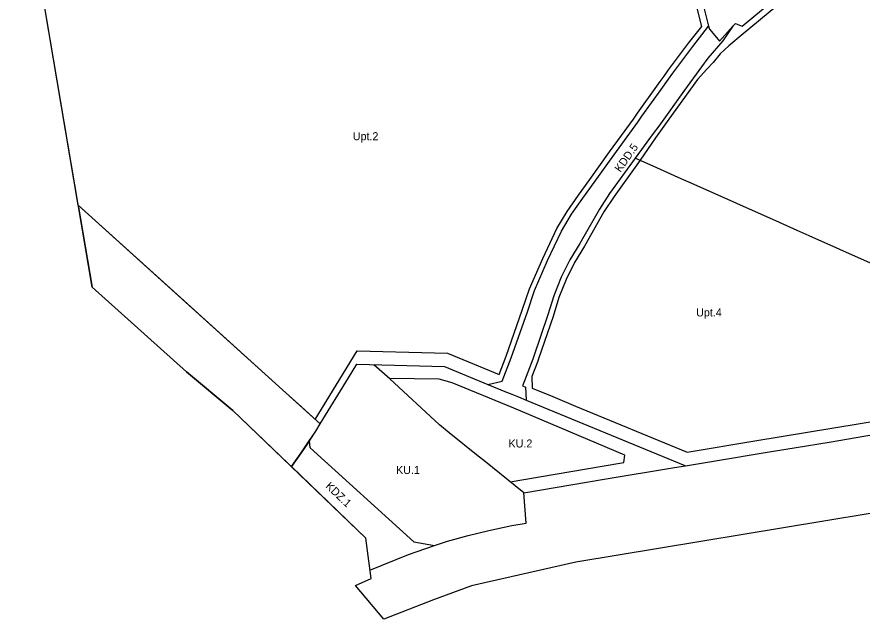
# Model space of a CAD drawing. Extents: x 7420092 to 7422347, y 5542930 to 5544880.
# Drawn here: x 7420112 to 7420746, y 5542930 to 5543382 of the extents above; entities that cross this region are included whole.
import ezdxf

# ---------------------------------------------------------------- set-up
doc = ezdxf.new("R2010")
doc.units = 0
for name, color, linetype in [('_informacja', 7, 'Continuous'), ('LIN_Granica Planu', 7, 'Continuous'), ('LIN_linie_rozgraniczajace', 7, 'Continuous'), ('LIN_linie_zabudowy_nieprzekraczalne', 7, 'Continuous'), ('LIN_linie_zabudowy_obowiazujace', 7, 'Continuous'), ('TXT_oznaczenia_przeznaczen', 7, 'Continuous')]:
    doc.layers.add(name, color=color, linetype=linetype)

msp = doc.modelspace()

# ---------------------------------------------------------------- linework, layer by layer
at = {"layer": '_informacja'}
msp.add_line((7420158.31, 5543240.28), (7420168.76, 5543178.79), dxfattribs=at)
for points in [[(7420345.55, 5543017.94), (7420332.05, 5543030.93), (7420325.03, 5543037.68), (7420318.01, 5543044.43), (7420325.4, 5543054.79), (7420330.85, 5543062.86), (7420336.3, 5543070.93), (7420339.63, 5543076.35), (7420325.5, 5543089.13), (7420311.38, 5543101.92), (7420234.85, 5543171.1), (7420158.31, 5543240.28)], [(7420158.31, 5543240.28), (7420158.31, 5543240.28)], [(7420168.76, 5543178.79), (7420239.3, 5543115.39), (7420274.17, 5543086.58), (7420345.55, 5543017.93)], [(7420345.55, 5543017.93), (7420345.55, 5543017.94)]]:
    msp.add_lwpolyline(points, dxfattribs=at)
at = {"layer": 'LIN_Granica Planu'}
msp.add_lwpolyline([(7420780.41, 5543013.99), (7420531.27, 5542972.7), (7420452.94, 5542955.03), (7420424.43, 5542944.65), (7420387.18, 5542930.09), (7420366.13, 5542955.32), (7420377.68, 5542960.57), (7420373.92, 5542990.64), (7420274.17, 5543086.58), (7420239.3, 5543115.39), (7420168.76, 5543178.79), (7420131.86, 5543395.95)], dxfattribs=at)
at = {"layer": 'LIN_linie_rozgraniczajace'}
for p, q in [((7420311.38, 5543101.92), (7420158.31, 5543240.28)), ((7420339.62, 5543076.36), (7420311.38, 5543101.92)), ((7420332.1, 5543058.43), (7420331.46, 5543063.76))]:
    msp.add_line(p, q, dxfattribs=at)
for points in [[(7420158.31, 5543240.28), (7420133.14, 5543388.41), (7420131.86, 5543395.95), (7420112.28, 5543390.12), (7420147.7, 5543606.58), (7420196.16, 5543606.89), (7420215.32, 5543734.84), (7420281.17, 5543725.5), (7420281.92, 5543731.73), (7420304.35, 5543913.04), (7420382.59, 5543894.39), (7420448.49, 5543883.65), (7420541.88, 5543881.8), (7420609.94, 5543892.89), (7420703.36, 5543908.11), (7420803.92, 5543915.01), (7420873.43, 5543931.24), (7420922.3, 5543950.87), (7421004.88, 5544011.37), (7421076.71, 5544063.59), (7421101.18, 5544081.42), (7421115.83, 5544090.14), (7421144.5, 5544103.8), (7421171.72, 5544113.18)], [(7421302.89, 5543592.78), (7421274.33, 5543546.19), (7421094.42, 5543322.19), (7421037.13, 5543251.97), (7420996.85, 5543202.6), (7420977.29, 5543178.63), (7420933.5, 5543125.4), (7420905.07, 5543091.23), (7420891.59, 5543074.52), (7420860.62, 5543049.84), (7420848.87, 5543043.43), (7420820.53, 5543027.17), (7420780.41, 5543013.99), (7420531.27, 5542972.7), (7420452.94, 5542955.03), (7420424.43, 5542944.65), (7420387.18, 5542930.09), (7420366.13, 5542955.32), (7420377.68, 5542960.57), (7420373.92, 5542990.64), (7420318, 5543044.42)], [(7420625.59, 5543394.82), (7420630.74, 5543374.45), (7420631.27, 5543372.39), (7420634.06, 5543369.05), (7420638.94, 5543363.21), (7420648.79, 5543374.61), (7420650.88, 5543376.56), (7420655.75, 5543374.54), (7420696.68, 5543408.66)], [(7420465.27, 5543106.06), (7420476.1, 5543108.45), (7420482.79, 5543125.91), (7420494.86, 5543160.33), (7420500.18, 5543176.32), (7420510.05, 5543198.82), (7420520.57, 5543220.91), (7420527.99, 5543233.55), (7420536.4, 5543245.57), (7420544.91, 5543257.28), (7420559.67, 5543277.92), (7420577.55, 5543302.52), (7420580.68, 5543307.01), (7420595.13, 5543327.17), (7420600.64, 5543334.85), (7420603.94, 5543339.42), (7420618.77, 5543359.32), (7420630.74, 5543374.45)], [(7420648.79, 5543374.61), (7420641.43, 5543363.45), (7420630.18, 5543350.55), (7420625.36, 5543344.12), (7420612.68, 5543326.5), (7420593.28, 5543299.62), (7420589.06, 5543294.22), (7420575.67, 5543275.67), (7420556.51, 5543249.1), (7420548.87, 5543237.43), (7420534.23, 5543211.74), (7420526.69, 5543199.38), (7420520.23, 5543186.41), (7420514.71, 5543172.53), (7420510.28, 5543158.26), (7420499.57, 5543126.45), (7420499, 5543124.98), (7420492.68, 5543108.8), (7420491.19, 5543104.83), (7420493.53, 5543103.91), (7420493.99, 5543094.22)], [(7420780.38, 5543141.3), (7420779.71, 5543152.53), (7420779.05, 5543163.76), (7420778.87, 5543166.85), (7420778.84, 5543167.35), (7420778.81, 5543167.85), (7420788.61, 5543180.5), (7420752.08, 5543196.79), (7420729.04, 5543207.03), (7420705.99, 5543217.27), (7420697, 5543221.32), (7420683.73, 5543227.28), (7420651.79, 5543241.53), (7420619.86, 5543255.78), (7420607.93, 5543261.1), (7420591.8, 5543268.38), (7420575.67, 5543275.67)], [(7420331.46, 5543063.76), (7420336.3, 5543070.93), (7420339.62, 5543076.36), (7420360.83, 5543111), (7420367.04, 5543121.15), (7420432.85, 5543119.43), (7420465.27, 5543106.06)], [(7420492.34, 5543024.67), (7420462.25, 5543048.95), (7420458.1, 5543052.3), (7420436.38, 5543069.83), (7420429.03, 5543075.76), (7420391.7, 5543110.15), (7420379.88, 5543120.81)], [(7420465.27, 5543106.06), (7420479.24, 5543100.29), (7420483.16, 5543098.68), (7420488.1, 5543096.65), (7420493.99, 5543094.22)], [(7420493.99, 5543094.22), (7420612.81, 5543045.21), (7420613.36, 5543044.99)], [(7420613.36, 5543044.99), (7420638.81, 5543049.21), (7420671.62, 5543054.65), (7420720.97, 5543062.83), (7420776.06, 5543072.24)], [(7420331.46, 5543063.76), (7420325.4, 5543054.79), (7420318, 5543044.42)], [(7420332.1, 5543058.43), (7420409.84, 5542987.94), (7420425.31, 5542985.33)], [(7420492.34, 5543024.67), (7420552.51, 5543034.91), (7420605.14, 5543043.63), (7420613.36, 5543044.99)], [(7420376.9, 5542966.78), (7420405.81, 5542978.6), (7420425.31, 5542985.33), (7420435.12, 5542988.39), (7420450.47, 5542992.75), (7420465.89, 5542996.5), (7420483.28, 5543000.21), (7420494.03, 5543002), (7420492.34, 5543024.67)]]:
    msp.add_lwpolyline(points, dxfattribs=at)
at = {"layer": 'LIN_linie_zabudowy_nieprzekraczalne'}
for points in [[(7420335.85, 5543079.77), (7420367.3, 5543131.15), (7420434.96, 5543129.38), (7420473.71, 5543113.4), (7420479.03, 5543127.29), (7420491.07, 5543161.62), (7420496.44, 5543177.76), (7420506.41, 5543200.48), (7420517.03, 5543222.79), (7420524.62, 5543235.71), (7420533.14, 5543247.89), (7420541.67, 5543259.62), (7420556.43, 5543280.26), (7420574.29, 5543304.84), (7420577.41, 5543309.32), (7420591.88, 5543329.5), (7420594.5, 5543333.16), (7420595.12, 5543334.02)], [(7420579.39, 5543273.99), (7420559.81, 5543246.83), (7420552.28, 5543235.34), (7420537.68, 5543209.71), (7420530.19, 5543197.44), (7420523.89, 5543184.78), (7420518.48, 5543171.2), (7420514.09, 5543157.03), (7420503.33, 5543125.09), (7420502.73, 5543123.53), (7420498.16, 5543111.83), (7420498.57, 5543103.24), (7420514.03, 5543096.85), (7420531.04, 5543089.82), (7420614.52, 5543055.32)], [(7420567.29, 5543047.49), (7420567.94, 5543053.03), (7420484.69, 5543088.29), (7420438.61, 5543107.2), (7420428.65, 5543109.9), (7420391.31, 5543110.51)]]:
    msp.add_lwpolyline(points, dxfattribs=at)
at = {"layer": 'LIN_linie_zabudowy_obowiazujace'}
for points in [[(7420595.12, 5543334.02), (7420597.39, 5543337.19), (7420600.71, 5543341.79), (7420615.6, 5543361.76), (7420625.6, 5543374.4), (7420621.37, 5543391.11), (7420591.21, 5543403.01), (7420567.61, 5543412.31), (7420554.15, 5543420.74), (7420543.34, 5543427.51), (7420524.88, 5543444.49), (7420522.94, 5543446.29), (7420518.77, 5543451.56), (7420514.64, 5543456.83), (7420510.16, 5543462.52), (7420495.61, 5543488.03), (7420482.04, 5543494.08), (7420413.4, 5543473.19)], [(7420802.74, 5543425.64), (7420780.67, 5543441.31), (7420752.09, 5543461.59), (7420741.91, 5543458.74), (7420730.62, 5543435.94), (7420716.57, 5543418.76), (7420699.88, 5543404.82), (7420656.63, 5543368.76), (7420645.82, 5543359.76), (7420639.42, 5543353.75), (7420634.07, 5543347.4), (7420629.42, 5543342.3), (7420622.32, 5543334.52), (7420600.86, 5543304.87), (7420590.88, 5543290.84), (7420579.39, 5543273.99)], [(7420614.52, 5543055.32), (7420665.35, 5543063.74), (7420763.91, 5543080.08), (7420766.65, 5543080.56), (7420771.29, 5543081.48), (7420783.7, 5543085.3), (7420793.88, 5543089.63), (7420811.3, 5543096.94), (7420822.08, 5543101.53), (7420829.51, 5543106.28), (7420834.97, 5543110.15), (7420838.9, 5543113.21), (7420858.08, 5543136.61), (7420924.27, 5543216.74), (7420974.49, 5543277.54), (7420977.82, 5543274.81), (7420991.92, 5543292.11)], [(7420481.96, 5543033.05), (7420550.85, 5543044.77), (7420567.29, 5543047.49)]]:
    msp.add_lwpolyline(points, dxfattribs=at)

# ---------------------------------------------------------------- texts
at = {"layer": 'TXT_oznaczenia_przeznaczen'}
for s, p in [('Upt.2', (7420364.04, 5543289.07)), ('Upt.4', (7420621.39, 5543156.99)), ('KU.2', (7420480.75, 5543058.73)), ('KU.1', (7420396.47, 5543038.88))]:
    msp.add_text(s, height=6, dxfattribs=at).set_placement(p)
for s, rotation, p in [('KDD.5', 54.70632, (7420564.64, 5543264.59)), ('KDZ.1', 316.19193, (7420343.12, 5543029.16))]:
    msp.add_text(s, height=6, rotation=rotation, dxfattribs=at).set_placement(p)

doc.saveas('drawing.dxf')
